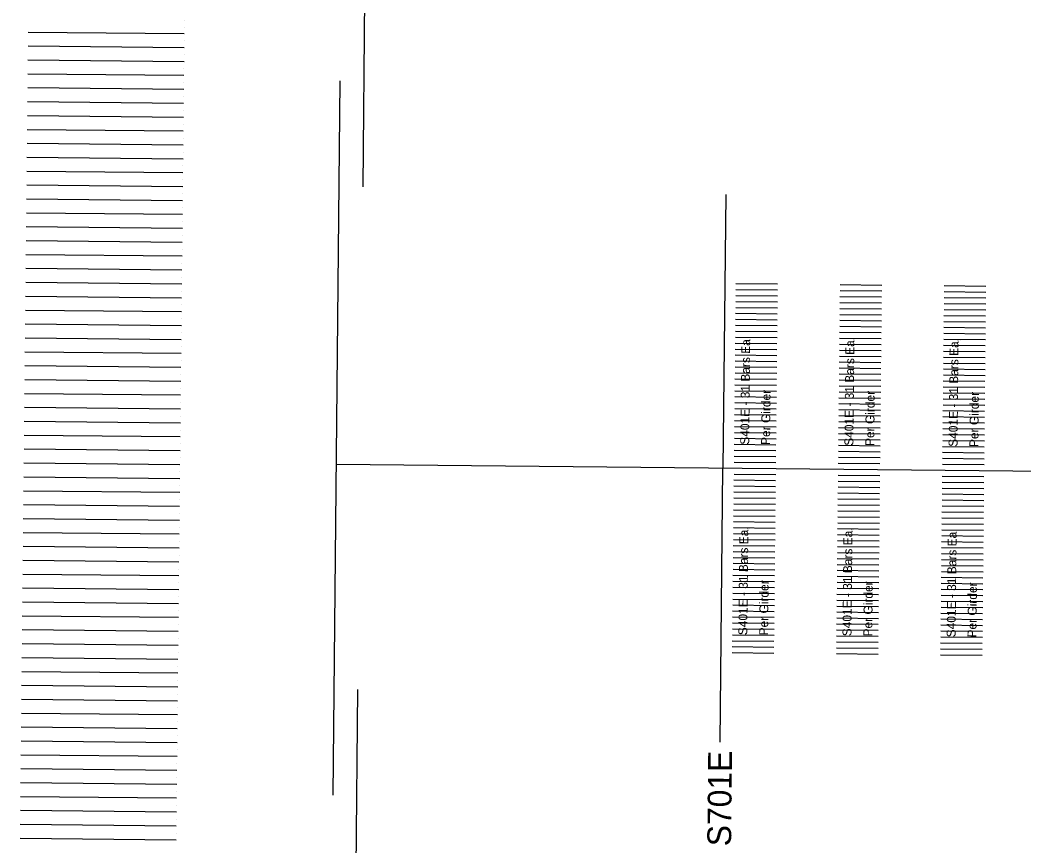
# Model space of a CAD drawing. Extents: x 632547 to 633311, y 380830 to 386139.
# Drawn here: x 633070.1 to 633154.5, y 380998.5 to 381067.9 of the extents above; entities that cross this region are included whole.
import ezdxf

# ---------------------------------------------------------------- set-up
doc = ezdxf.new("R2010")
doc.units = 0
for name, color, linetype in [('B_Border', 7, 'Continuous'), ('R_Border_Scale', 7, 'Continuous'), ('R_Wall', 7, 'Continuous')]:
    doc.layers.add(name, color=color, linetype=linetype)

msp = doc.modelspace()

# ---------------------------------------------------------------- linework, layer by layer
at = {"layer": 'B_Border'}
msp.add_line((633213.74, 381029.408), (633096.686, 381030.593), dxfattribs=at)
at = {"layer": 'R_Border_Scale'}
for p, q in [((633099.529, 381113.901), (633098.922, 381053.904)), ((633083.951, 381067.914), (633083.951, 381067.914)), ((633083.939, 381066.747), (633070.828, 381066.879)), ((633083.939, 381066.747), (633083.939, 381066.747)), ((633083.945, 381067.33), (633083.945, 381067.33)), ((633083.927, 381065.579), (633070.816, 381065.712)), ((633083.933, 381066.163), (633083.933, 381066.163)), ((633083.921, 381064.996), (633083.921, 381064.996)), ((633083.927, 381065.579), (633083.927, 381065.579)), ((633083.916, 381064.412), (633070.804, 381064.545)), ((633083.916, 381064.412), (633083.916, 381064.412)), ((633083.904, 381063.245), (633070.793, 381063.377)), ((633083.904, 381063.245), (633083.904, 381063.245)), ((633083.91, 381063.828), (633083.91, 381063.828)), ((633083.898, 381062.661), (633083.898, 381062.661)), ((633097.012, 381062.813), (633096.405, 381002.816)), ((633083.892, 381062.077), (633070.781, 381062.21)), ((633083.886, 381061.493), (633083.886, 381061.493)), ((633083.892, 381062.077), (633083.892, 381062.077)), ((633083.88, 381060.91), (633070.769, 381061.042)), ((633083.88, 381060.91), (633083.88, 381060.91)), ((633083.868, 381059.742), (633070.757, 381059.875)), ((633083.874, 381060.326), (633083.874, 381060.326)), ((633083.862, 381059.159), (633083.862, 381059.159)), ((633083.868, 381059.742), (633083.868, 381059.742)), ((633083.856, 381058.575), (633070.745, 381058.708)), ((633083.856, 381058.575), (633083.856, 381058.575)), ((633083.845, 381057.408), (633070.733, 381057.54)), ((633083.845, 381057.408), (633083.845, 381057.408)), ((633083.851, 381057.991), (633083.851, 381057.991)), ((633083.839, 381056.824), (633083.839, 381056.824)), ((633083.833, 381056.24), (633070.722, 381056.373)), ((633083.827, 381055.657), (633083.827, 381055.657)), ((633083.833, 381056.24), (633083.833, 381056.24)), ((633083.821, 381055.073), (633070.71, 381055.206)), ((633083.821, 381055.073), (633083.821, 381055.073)), ((633083.809, 381053.906), (633070.698, 381054.038)), ((633083.809, 381053.906), (633083.809, 381053.906)), ((633083.815, 381054.489), (633083.815, 381054.489)), ((633083.803, 381053.322), (633083.803, 381053.322)), ((633129.421, 381053.263), (633129.188, 381030.264)), ((633083.797, 381052.738), (633070.686, 381052.871)), ((633083.797, 381052.738), (633083.797, 381052.738)), ((633083.786, 381051.571), (633070.674, 381051.704)), ((633083.786, 381051.571), (633083.786, 381051.571)), ((633083.792, 381052.155), (633083.792, 381052.155)), ((633083.774, 381050.404), (633070.663, 381050.536)), ((633083.78, 381050.987), (633083.78, 381050.987)), ((633083.768, 381049.82), (633083.768, 381049.82)), ((633083.774, 381050.404), (633083.774, 381050.404)), ((633083.762, 381049.236), (633070.651, 381049.369)), ((633083.762, 381049.236), (633083.762, 381049.236)), ((633083.75, 381048.069), (633070.639, 381048.202)), ((633083.75, 381048.069), (633083.75, 381048.069)), ((633083.756, 381048.653), (633083.756, 381048.653)), ((633083.744, 381047.485), (633083.744, 381047.485)), ((633083.738, 381046.902), (633070.627, 381047.034)), ((633083.732, 381046.318), (633083.732, 381046.318)), ((633083.738, 381046.902), (633083.738, 381046.902)), ((633083.727, 381045.734), (633070.615, 381045.867)), ((633083.727, 381045.734), (633083.727, 381045.734)), ((633133.776, 381045.718), (633130.276, 381045.754)), ((633142.525, 381045.63), (633139.025, 381045.665)), ((633151.275, 381045.541), (633147.775, 381045.577)), ((633083.715, 381044.567), (633070.604, 381044.699)), ((633083.721, 381045.15), (633083.721, 381045.15)), ((633133.765, 381044.718), (633130.266, 381044.754)), ((633133.771, 381045.218), (633130.271, 381045.254)), ((633142.515, 381044.63), (633139.015, 381044.665)), ((633142.52, 381045.13), (633139.02, 381045.165)), ((633151.27, 381045.041), (633147.77, 381045.077)), ((633083.709, 381043.983), (633083.709, 381043.983)), ((633083.715, 381044.567), (633083.715, 381044.567)), ((633133.76, 381044.218), (633130.261, 381044.254)), ((633142.51, 381044.13), (633139.01, 381044.165)), ((633151.26, 381044.041), (633147.76, 381044.077)), ((633151.265, 381044.541), (633147.765, 381044.577)), ((633083.703, 381043.399), (633070.592, 381043.532)), ((633083.703, 381043.399), (633083.703, 381043.399)), ((633133.75, 381043.218), (633130.251, 381043.254)), ((633133.755, 381043.718), (633130.256, 381043.754)), ((633142.5, 381043.13), (633139, 381043.165)), ((633142.505, 381043.63), (633139.005, 381043.665)), ((633151.249, 381043.041), (633147.75, 381043.077)), ((633151.254, 381043.541), (633147.755, 381043.577)), ((633083.691, 381042.232), (633070.58, 381042.365)), ((633083.691, 381042.232), (633083.691, 381042.232)), ((633083.697, 381042.816), (633083.697, 381042.816)), ((633133.74, 381042.218), (633130.24, 381042.254)), ((633133.745, 381042.718), (633130.245, 381042.754)), ((633142.49, 381042.13), (633138.99, 381042.165)), ((633142.495, 381042.63), (633138.995, 381042.665)), ((633151.244, 381042.541), (633147.745, 381042.577)), ((633083.685, 381041.648), (633083.685, 381041.648)), ((633133.73, 381041.219), (633130.23, 381041.254)), ((633133.735, 381041.718), (633130.235, 381041.754)), ((633142.485, 381041.63), (633138.985, 381041.665)), ((633151.234, 381041.541), (633147.734, 381041.577)), ((633151.239, 381042.041), (633147.739, 381042.077)), ((633083.679, 381041.065), (633070.568, 381041.197)), ((633083.673, 381040.481), (633083.673, 381040.481)), ((633083.679, 381041.065), (633083.679, 381041.065)), ((633133.725, 381040.719), (633130.225, 381040.754)), ((633142.475, 381040.63), (633138.975, 381040.665)), ((633142.48, 381041.13), (633138.98, 381041.165)), ((633151.224, 381040.542), (633147.724, 381040.577)), ((633151.229, 381041.041), (633147.729, 381041.077)), ((633083.667, 381039.897), (633070.556, 381040.03)), ((633083.667, 381039.897), (633083.667, 381039.897)), ((633133.715, 381039.719), (633130.215, 381039.754)), ((633133.72, 381040.219), (633130.22, 381040.254)), ((633142.464, 381039.63), (633138.965, 381039.665)), ((633142.47, 381040.13), (633138.97, 381040.165)), ((633151.214, 381039.542), (633147.714, 381039.577)), ((633151.219, 381040.042), (633147.719, 381040.077)), ((633083.656, 381038.73), (633070.545, 381038.863)), ((633083.656, 381038.73), (633083.656, 381038.73)), ((633083.662, 381039.314), (633083.662, 381039.314)), ((633133.705, 381038.719), (633130.205, 381038.754)), ((633133.71, 381039.219), (633130.21, 381039.254)), ((633142.459, 381039.13), (633138.96, 381039.166)), ((633151.209, 381039.042), (633147.709, 381039.077)), ((633083.65, 381038.146), (633083.65, 381038.146)), ((633133.7, 381038.219), (633130.2, 381038.254)), ((633142.449, 381038.13), (633138.949, 381038.166)), ((633142.454, 381038.63), (633138.955, 381038.666)), ((633151.199, 381038.042), (633147.699, 381038.077)), ((633151.204, 381038.542), (633147.704, 381038.577)), ((633083.644, 381037.563), (633070.533, 381037.695)), ((633083.644, 381037.563), (633083.644, 381037.563)), ((633133.69, 381037.219), (633130.19, 381037.254)), ((633133.695, 381037.719), (633130.195, 381037.754)), ((633142.439, 381037.13), (633138.939, 381037.166)), ((633142.444, 381037.63), (633138.944, 381037.666)), ((633151.189, 381037.042), (633147.689, 381037.077)), ((633151.194, 381037.542), (633147.694, 381037.577)), ((633083.632, 381036.395), (633070.521, 381036.528)), ((633083.632, 381036.395), (633083.632, 381036.395)), ((633083.638, 381036.979), (633083.638, 381036.979)), ((633133.68, 381036.219), (633130.18, 381036.254)), ((633133.685, 381036.719), (633130.185, 381036.754)), ((633142.434, 381036.63), (633138.934, 381036.666)), ((633151.184, 381036.542), (633147.684, 381036.577)), ((633083.62, 381035.228), (633070.509, 381035.361)), ((633083.626, 381035.812), (633083.626, 381035.812)), ((633133.674, 381035.719), (633130.175, 381035.754)), ((633142.424, 381035.63), (633138.924, 381035.666)), ((633142.429, 381036.13), (633138.929, 381036.166)), ((633151.174, 381035.542), (633147.674, 381035.577)), ((633151.179, 381036.042), (633147.679, 381036.077)), ((633083.614, 381034.644), (633083.614, 381034.644)), ((633083.62, 381035.228), (633083.62, 381035.228)), ((633133.664, 381034.719), (633130.165, 381034.754)), ((633133.669, 381035.219), (633130.17, 381035.254)), ((633142.414, 381034.63), (633138.914, 381034.666)), ((633142.419, 381035.13), (633138.919, 381035.166)), ((633151.163, 381034.542), (633147.664, 381034.577)), ((633151.168, 381035.042), (633147.669, 381035.077)), ((633083.608, 381034.061), (633070.497, 381034.193)), ((633083.608, 381034.061), (633083.608, 381034.061)), ((633133.654, 381033.719), (633130.154, 381033.754)), ((633133.659, 381034.219), (633130.159, 381034.254)), ((633142.404, 381033.63), (633138.904, 381033.666)), ((633142.409, 381034.13), (633138.909, 381034.166)), ((633151.158, 381034.042), (633147.659, 381034.077)), ((633083.597, 381032.893), (633070.485, 381033.026)), ((633083.597, 381032.893), (633083.597, 381032.893)), ((633083.603, 381033.477), (633083.603, 381033.477)), ((633133.649, 381033.219), (633130.149, 381033.254)), ((633142.399, 381033.13), (633138.899, 381033.166)), ((633151.148, 381033.042), (633147.648, 381033.077)), ((633151.153, 381033.542), (633147.653, 381033.577)), ((633083.591, 381032.31), (633083.591, 381032.31)), ((633133.639, 381032.219), (633130.139, 381032.254)), ((633133.644, 381032.719), (633130.144, 381032.754)), ((633142.389, 381032.13), (633138.889, 381032.166)), ((633142.394, 381032.63), (633138.894, 381032.666)), ((633151.138, 381032.042), (633147.638, 381032.077)), ((633151.143, 381032.542), (633147.643, 381032.577)), ((633083.585, 381031.726), (633070.474, 381031.859)), ((633083.579, 381031.142), (633083.579, 381031.142)), ((633083.585, 381031.726), (633083.585, 381031.726)), ((633133.629, 381031.219), (633130.129, 381031.254)), ((633133.634, 381031.719), (633130.134, 381031.754)), ((633142.378, 381031.131), (633138.879, 381031.166)), ((633142.384, 381031.63), (633138.884, 381031.666)), ((633151.133, 381031.542), (633147.633, 381031.577)), ((633083.573, 381030.559), (633070.462, 381030.691)), ((633083.573, 381030.559), (633083.573, 381030.559)), ((633133.624, 381030.719), (633130.124, 381030.754)), ((633142.373, 381030.631), (633138.874, 381030.666)), ((633151.123, 381030.542), (633147.623, 381030.577)), ((633151.128, 381031.042), (633147.628, 381031.077)), ((633083.561, 381029.391), (633070.45, 381029.524)), ((633083.567, 381029.975), (633083.567, 381029.975)), ((633128.956, 381007.265), (633129.188, 381030.264)), ((633133.614, 381029.719), (633130.114, 381029.755)), ((633142.363, 381029.631), (633138.863, 381029.666)), ((633151.113, 381029.542), (633147.613, 381029.577)), ((633083.555, 381028.808), (633083.555, 381028.808)), ((633083.561, 381029.391), (633083.561, 381029.391)), ((633133.604, 381028.719), (633130.104, 381028.755)), ((633133.609, 381029.219), (633130.109, 381029.255)), ((633142.353, 381028.631), (633138.853, 381028.666)), ((633142.358, 381029.131), (633138.858, 381029.166)), ((633151.108, 381029.042), (633147.608, 381029.077)), ((633083.549, 381028.224), (633070.438, 381028.356)), ((633083.549, 381028.224), (633083.549, 381028.224)), ((633133.599, 381028.219), (633130.099, 381028.255)), ((633142.348, 381028.131), (633138.848, 381028.166)), ((633151.098, 381028.042), (633147.598, 381028.078)), ((633151.103, 381028.542), (633147.603, 381028.578)), ((633083.538, 381027.056), (633070.426, 381027.189)), ((633083.538, 381027.056), (633083.538, 381027.056)), ((633083.543, 381027.64), (633083.543, 381027.64)), ((633133.588, 381027.219), (633130.089, 381027.255)), ((633133.594, 381027.719), (633130.094, 381027.755)), ((633142.338, 381027.131), (633138.838, 381027.166)), ((633142.343, 381027.631), (633138.843, 381027.666)), ((633151.088, 381027.042), (633147.588, 381027.078)), ((633151.093, 381027.542), (633147.593, 381027.578)), ((633083.532, 381026.473), (633083.532, 381026.473)), ((633133.578, 381026.219), (633130.079, 381026.255)), ((633133.583, 381026.719), (633130.084, 381026.755)), ((633142.328, 381026.131), (633138.828, 381026.166)), ((633142.333, 381026.631), (633138.833, 381026.666)), ((633151.077, 381026.042), (633147.578, 381026.078)), ((633151.083, 381026.542), (633147.583, 381026.578)), ((633083.526, 381025.889), (633070.415, 381026.022)), ((633083.52, 381025.305), (633083.52, 381025.305)), ((633083.526, 381025.889), (633083.526, 381025.889)), ((633133.568, 381025.219), (633130.068, 381025.255)), ((633133.573, 381025.719), (633130.073, 381025.755)), ((633142.323, 381025.631), (633138.823, 381025.666)), ((633151.072, 381025.542), (633147.573, 381025.578)), ((633083.514, 381024.722), (633070.403, 381024.854)), ((633083.514, 381024.722), (633083.514, 381024.722)), ((633133.563, 381024.719), (633130.063, 381024.755)), ((633142.313, 381024.631), (633138.813, 381024.666)), ((633142.318, 381025.131), (633138.818, 381025.166)), ((633151.062, 381024.542), (633147.562, 381024.578)), ((633151.067, 381025.042), (633147.568, 381025.078)), ((633083.502, 381023.554), (633070.391, 381023.687)), ((633083.502, 381023.554), (633083.502, 381023.554)), ((633083.508, 381024.138), (633083.508, 381024.138)), ((633133.553, 381023.719), (633130.053, 381023.755)), ((633133.558, 381024.219), (633130.058, 381024.255)), ((633142.303, 381023.631), (633138.803, 381023.666)), ((633142.308, 381024.131), (633138.808, 381024.166)), ((633151.052, 381023.542), (633147.552, 381023.578)), ((633151.057, 381024.042), (633147.557, 381024.078)), ((633083.496, 381022.971), (633083.496, 381022.971)), ((633133.543, 381022.719), (633130.043, 381022.755)), ((633133.548, 381023.219), (633130.048, 381023.255)), ((633142.298, 381023.131), (633138.798, 381023.166)), ((633151.047, 381023.042), (633147.547, 381023.078)), ((633083.49, 381022.387), (633070.379, 381022.52)), ((633083.49, 381022.387), (633083.49, 381022.387)), ((633133.538, 381022.219), (633130.038, 381022.255)), ((633142.287, 381022.131), (633138.788, 381022.166)), ((633142.292, 381022.631), (633138.793, 381022.666)), ((633151.037, 381022.042), (633147.537, 381022.078)), ((633151.042, 381022.542), (633147.542, 381022.578)), ((633083.479, 381021.22), (633070.367, 381021.352)), ((633083.479, 381021.22), (633083.479, 381021.22)), ((633083.484, 381021.803), (633083.484, 381021.803)), ((633133.528, 381021.22), (633130.028, 381021.255)), ((633133.533, 381021.72), (633130.033, 381021.755)), ((633142.277, 381021.131), (633138.777, 381021.166)), ((633142.282, 381021.631), (633138.783, 381021.666)), ((633151.027, 381021.042), (633147.527, 381021.078)), ((633151.032, 381021.542), (633147.532, 381021.578)), ((633083.467, 381020.052), (633070.356, 381020.185)), ((633083.473, 381020.636), (633083.473, 381020.636)), ((633133.518, 381020.22), (633130.018, 381020.255)), ((633133.523, 381020.72), (633130.023, 381020.755)), ((633142.267, 381020.131), (633138.767, 381020.166)), ((633142.272, 381020.631), (633138.772, 381020.666)), ((633151.022, 381020.543), (633147.522, 381020.578)), ((633083.461, 381019.469), (633083.461, 381019.469)), ((633083.467, 381020.052), (633083.467, 381020.052)), ((633133.513, 381019.72), (633130.013, 381019.755)), ((633142.262, 381019.631), (633138.762, 381019.667)), ((633151.012, 381019.543), (633147.512, 381019.578)), ((633151.017, 381020.043), (633147.517, 381020.078)), ((633083.455, 381018.885), (633070.344, 381019.018)), ((633083.455, 381018.885), (633083.455, 381018.885)), ((633133.502, 381018.72), (633130.003, 381018.755)), ((633133.508, 381019.22), (633130.008, 381019.255)), ((633142.252, 381018.631), (633138.752, 381018.667)), ((633142.257, 381019.131), (633138.757, 381019.167)), ((633151.002, 381018.543), (633147.502, 381018.578)), ((633151.007, 381019.043), (633147.507, 381019.078)), ((633083.443, 381017.718), (633070.332, 381017.85)), ((633083.443, 381017.718), (633083.443, 381017.718)), ((633083.449, 381018.301), (633083.449, 381018.301)), ((633133.492, 381017.72), (633129.993, 381017.755)), ((633133.497, 381018.22), (633129.998, 381018.255)), ((633142.242, 381017.631), (633138.742, 381017.667)), ((633142.247, 381018.131), (633138.747, 381018.167)), ((633150.997, 381018.043), (633147.497, 381018.078)), ((633083.437, 381017.134), (633083.437, 381017.134)), ((633133.487, 381017.22), (633129.987, 381017.255)), ((633142.237, 381017.131), (633138.737, 381017.167)), ((633150.986, 381017.043), (633147.487, 381017.078)), ((633150.991, 381017.543), (633147.492, 381017.578)), ((633083.431, 381016.55), (633070.32, 381016.683)), ((633083.425, 381015.967), (633083.425, 381015.967)), ((633083.431, 381016.55), (633083.431, 381016.55)), ((633133.477, 381016.22), (633129.977, 381016.255)), ((633133.482, 381016.72), (633129.982, 381016.755)), ((633142.227, 381016.131), (633138.727, 381016.167)), ((633142.232, 381016.631), (633138.732, 381016.667)), ((633150.976, 381016.043), (633147.476, 381016.078)), ((633150.981, 381016.543), (633147.482, 381016.578)), ((633083.419, 381015.383), (633070.308, 381015.516)), ((633083.419, 381015.383), (633083.419, 381015.383)), ((633133.467, 381015.22), (633129.967, 381015.255)), ((633133.472, 381015.72), (633129.972, 381015.755)), ((633142.217, 381015.131), (633138.717, 381015.167)), ((633142.222, 381015.631), (633138.722, 381015.667)), ((633150.971, 381015.543), (633147.471, 381015.578)), ((633083.408, 381014.216), (633070.297, 381014.348)), ((633083.414, 381014.799), (633083.414, 381014.799)), ((633133.462, 381014.72), (633129.962, 381014.755)), ((633142.212, 381014.631), (633138.712, 381014.667)), ((633150.961, 381014.543), (633147.461, 381014.578)), ((633150.966, 381015.043), (633147.466, 381015.078)), ((633083.402, 381013.632), (633083.402, 381013.632)), ((633083.408, 381014.216), (633083.408, 381014.216)), ((633083.396, 381013.048), (633070.285, 381013.181)), ((633083.396, 381013.048), (633083.396, 381013.048)), ((633083.384, 381011.881), (633070.273, 381012.013)), ((633083.384, 381011.881), (633083.384, 381011.881)), ((633083.39, 381012.465), (633083.39, 381012.465)), ((633083.378, 381011.297), (633083.378, 381011.297)), ((633098.495, 381011.684), (633097.888, 380951.688)), ((633083.372, 381010.713), (633070.261, 381010.846)), ((633083.366, 381010.13), (633083.366, 381010.13)), ((633083.372, 381010.713), (633083.372, 381010.713)), ((633083.36, 381009.546), (633070.249, 381009.679)), ((633083.36, 381009.546), (633083.36, 381009.546)), ((633083.349, 381008.379), (633070.237, 381008.511)), ((633083.349, 381008.379), (633083.349, 381008.379)), ((633083.355, 381008.962), (633083.355, 381008.962)), ((633083.343, 381007.795), (633083.343, 381007.795)), ((633083.337, 381007.211), (633070.226, 381007.344)), ((633083.337, 381007.211), (633083.337, 381007.211)), ((633083.325, 381006.044), (633070.214, 381006.177)), ((633083.325, 381006.044), (633083.325, 381006.044)), ((633083.331, 381006.628), (633083.331, 381006.628)), ((633083.313, 381004.877), (633070.202, 381005.009)), ((633083.319, 381005.46), (633083.319, 381005.46)), ((633083.307, 381004.293), (633083.307, 381004.293)), ((633083.313, 381004.877), (633083.313, 381004.877)), ((633083.301, 381003.709), (633070.19, 381003.842)), ((633083.301, 381003.709), (633083.301, 381003.709)), ((633083.29, 381002.542), (633070.178, 381002.675)), ((633083.29, 381002.542), (633083.29, 381002.542)), ((633083.295, 381003.126), (633083.295, 381003.126)), ((633083.284, 381001.958), (633083.284, 381001.958)), ((633083.278, 381001.375), (633070.167, 381001.507)), ((633083.272, 381000.791), (633083.272, 381000.791)), ((633083.278, 381001.375), (633083.278, 381001.375)), ((633083.266, 381000.207), (633070.155, 381000.34)), ((633083.266, 381000.207), (633083.266, 381000.207)), ((633083.254, 380999.04), (633070.143, 380999.173)), ((633083.26, 380999.624), (633083.26, 380999.624)), ((633083.254, 380999.04), (633083.254, 380999.04))]:
    msp.add_line(p, q, dxfattribs=at)

# ---------------------------------------------------------------- texts
at = {"layer": 'R_Wall'}
for s, height, p in [('S401E - 31 Bars Ea,', 0.75, (633131.389, 381032.242)), ('S401E - 31 Bars Ea,', 0.75, (633140.139, 381032.153)), ('S401E - 31 Bars Ea,', 0.75, (633148.888, 381032.065)), ('Per Girder', 0.75, (633133.139, 381032.224)), ('Per Girder', 0.75, (633141.889, 381032.136)), ('Per Girder', 0.75, (633150.638, 381032.047)), ('S401E - 31 Bars Ea,', 0.75, (633131.227, 381016.242)), ('S401E - 31 Bars Ea,', 0.75, (633139.977, 381016.154)), ('S401E - 31 Bars Ea,', 0.75, (633148.726, 381016.065)), ('Per Girder', 0.75, (633132.977, 381016.225)), ('Per Girder', 0.75, (633141.727, 381016.137)), ('Per Girder', 0.75, (633150.476, 381016.048)), ('S701E', 2, (633129.868, 380998.505))]:
    msp.add_text(s, height=height, rotation=89.43036, dxfattribs=at).set_placement(p)

doc.saveas('drawing.dxf')
